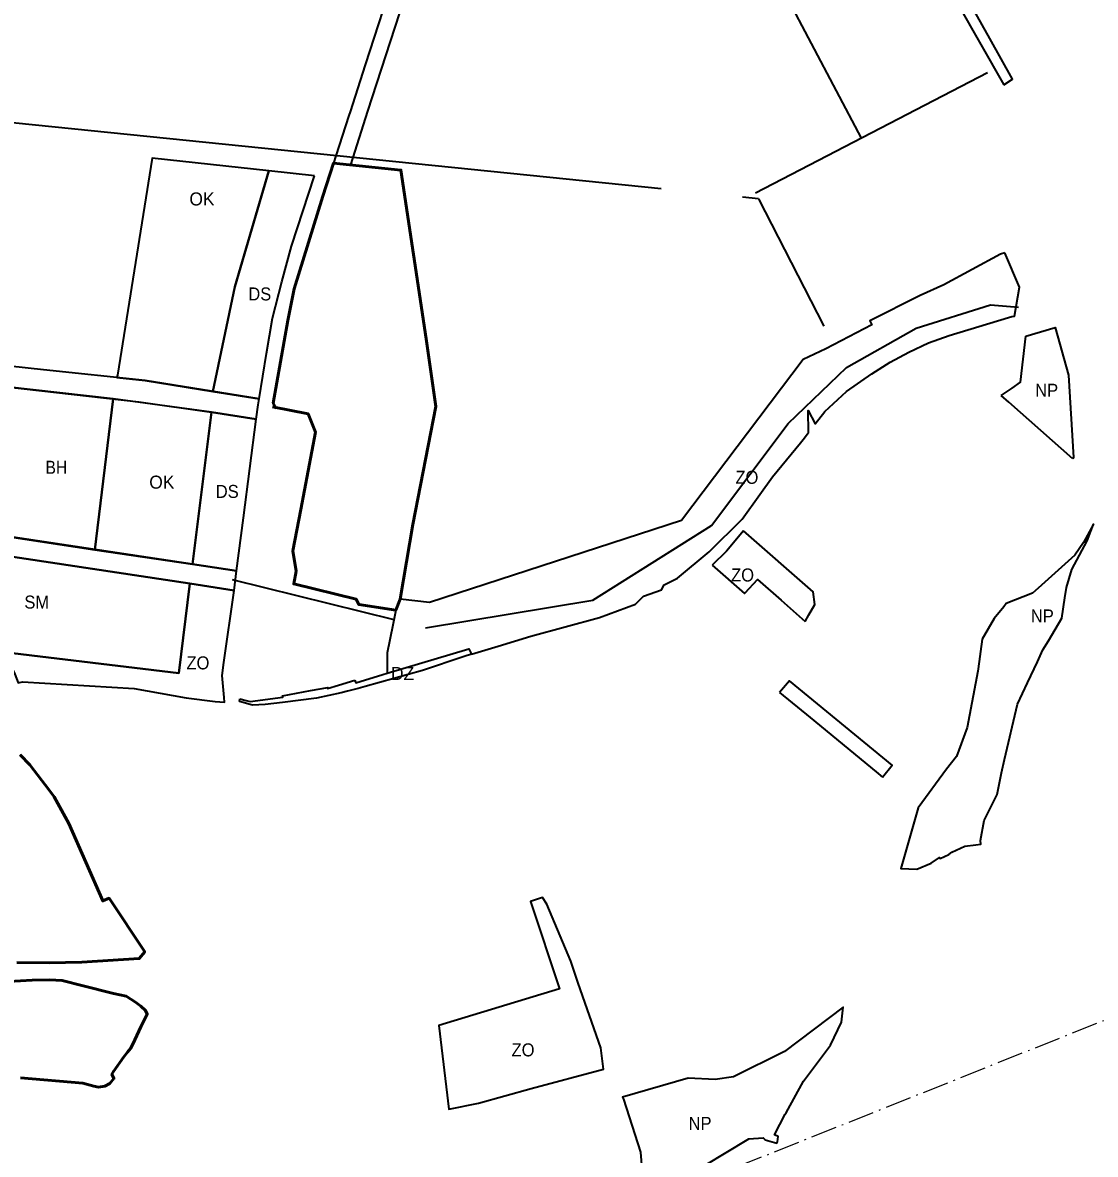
# Model space of a CAD drawing. Extents: x -650276 to -642489, y -1074311 to -1066658.
# Drawn here: x -646929 to -645941, y -1070271 to -1069228 of the extents above; entities that cross this region are included whole.
import ezdxf

# ---------------------------------------------------------------- set-up
doc = ezdxf.new("R2010")
doc.units = 0
doc.header["$LTSCALE"] = 4.8
doc.linetypes.add('DOT_DASHED', pattern=[7.7, 5, -1.2, 0.3, -1.2])
for name, color, linetype, lineweight in [('1', 7, 'Continuous', 35), ('13', 7, 'Continuous', 35), ('15', 7, 'Continuous', 35), ('18', 7, 'Continuous', 35), ('24', 7, 'Continuous', 35), ('25', 7, 'Continuous', 35), ('42', 7, 'Continuous', 35), ('48', 7, 'Continuous', 35), ('54', 7, 'Continuous', 35), ('55', 7, 'Continuous', 53), ('60', 7, 'Continuous', 53)]:
    doc.layers.add(name, color=color, linetype=linetype, lineweight=lineweight)
doc.layers.add('62', color=7, linetype='Continuous')

msp = doc.modelspace()

# ---------------------------------------------------------------- linework, layer by layer
at = {"layer": '1'}
msp.add_lwpolyline([(-646944.168, -1069563.743), (-647047.648, -1069552.245), (-647061.304, -1069551.773), (-647060.7, -1069683.894), (-646863, -1069714), (-646846, -1069575)], close=True, dxfattribs=at)
at = {"layer": '13'}
for points in [[(-646816.615, -1069558.064), (-646754.066, -1069567.993), (-646733.74, -1069471.688), (-646733.74, -1069471.688), (-646702.425, -1069364.771), (-646702.425, -1069364.771), (-646702.425, -1069364.771), (-646702.425, -1069364.771), (-646702.425, -1069364.771), (-646809.879, -1069353.002), (-646842.103, -1069553.182), (-646842.441, -1069555.283), (-646816.615, -1069558.064)], [(-646772.906, -1069727.176), (-646755.269, -1069587.04), (-646846, -1069575), (-646863, -1069714)]]:
    msp.add_lwpolyline(points, close=True, dxfattribs=at)
at = {"layer": '15'}
msp.add_line((-646142.68, -1069918.62), (-646136.88, -1069923.39), dxfattribs=at)
for points in [[(-646037.99, -1069242.88), (-646107, -1069119.41), (-646150.87, -1069037.64), (-646152.26, -1069038.76), (-646161.484, -1069046.228), (-646153.307, -1069059.947), (-646025.14, -1069285.394)], [(-646025.14, -1069285.394), (-646017.15, -1069280.19), (-646037.99, -1069242.88)], [(-646944.167, -1069563.743), (-646822.169, -1069577.72), (-646755.269, -1069587.04), (-646714.037, -1069593.585), (-646712.34, -1069580.49), (-646711.444, -1069574.771), (-646711.442, -1069574.759), (-646816.615, -1069558.064), (-646910.029, -1069548.006), (-646986.633, -1069539.757)], [(-647060.617, -1069702.116), (-646998.56, -1069711.443), (-646993.771, -1069712.163), (-646775.286, -1069745.022), (-646734.48, -1069751.35), (-646732.143, -1069733.308), (-646772.906, -1069727.176), (-646842.148, -1069716.763), (-647060.7, -1069683.894), (-647061.304, -1069551.773), (-647083.356, -1069551.018)], [(-646136.88, -1069923.39), (-646127.987, -1069912.574), (-646222.694, -1069834.722), (-646231.73, -1069845.42)], [(-646231.73, -1069845.42), (-646203.48, -1069868.65), (-646142.68, -1069918.62)]]:
    msp.add_lwpolyline(points, dxfattribs=at)
at = {"layer": '18'}
msp.add_lwpolyline([(-646785.437, -1069827.534), (-646775.286, -1069745.022), (-646993.771, -1069712.163), (-646981.92, -1069734.86), (-646946.369, -1069808.291)], close=True, dxfattribs=at)
msp.add_lwpolyline([(-646934.63, -1070094.24), (-646904.97, -1070094.52), (-646874.9, -1070094.1), (-646859.29, -1070093.1), (-646821.89, -1070090.7), (-646817.15, -1070084.76), (-646816.9, -1070084.45), (-646837.65, -1070053.22), (-646849.79, -1070035.17), (-646855.62, -1070037.66), (-646886.85, -1069966.26), (-646900.26, -1069941.64), (-646904.72, -1069935.84), (-646922.79, -1069912.31), (-646931.67, -1069902.89)], dxfattribs=at)
at = {"layer": '24'}
msp.add_line((-646772.907, -1069727.177), (-646732.143, -1069733.308), dxfattribs=at)
msp.add_lwpolyline([(-646660.526, -1069369.36), (-646702.425, -1069364.771), (-646733.74, -1069471.688), (-646754.066, -1069567.993), (-646711.442, -1069574.759), (-646704.68, -1069533.06), (-646699.07, -1069500.57), (-646690.51, -1069466.97), (-646681.5, -1069434.17)], close=True, dxfattribs=at)
for points in [[(-646725.82, -1069684.5), (-646714.037, -1069593.585), (-646755.269, -1069587.04), (-646772.907, -1069727.177)], [(-646732.143, -1069733.308), (-646725.82, -1069684.5), (-646725.82, -1069684.5)]]:
    msp.add_lwpolyline(points, dxfattribs=at)
at = {"layer": '25'}
msp.add_line((-646729.54, -1069853.69), (-646729.24, -1069851.41), dxfattribs=at)
for points in [[(-646515.63, -1069810.24), (-646522.32, -1069812.28), (-646560.92, -1069825.33), (-646613.65, -1069840.02), (-646620.06, -1069841.69), (-646629.83, -1069844.23), (-646635.93, -1069845.82), (-646658.5, -1069850.59), (-646689.73, -1069854.58), (-646705.87, -1069856.62), (-646717.66, -1069857.11), (-646729.54, -1069853.69)], [(-646593.34, -1069827.68), (-646518.19, -1069805.27), (-646515.63, -1069810.24)], [(-646623.31, -1069834.1), (-646622.54, -1069835.88), (-646622.19, -1069836.71), (-646597.29, -1069828.86), (-646593.34, -1069827.68)], [(-646729.24, -1069851.41), (-646723.5, -1069852.83), (-646719.82, -1069853.78), (-646689.63, -1069849.7), (-646689.8, -1069848.71), (-646664.22, -1069843.72), (-646648.18, -1069841.04), (-646648.28, -1069841.78), (-646638.34, -1069838.73), (-646623.31, -1069834.1)]]:
    msp.add_lwpolyline(points, dxfattribs=at)
at = {"layer": '42'}
msp.add_line((-646230.3, -1069760.5), (-646208.135, -1069779.937), dxfattribs=at)
for points in [[(-646589.56, -1069192.07), (-646601.41, -1069229.34), (-646613.6, -1069267.04), (-646627.59, -1069310.34), (-646628.66, -1069313.66), (-646640.715, -1069350.951), (-646642.89, -1069357.68), (-646626.774, -1069359.349), (-646611.107, -1069309.68), (-646577.878, -1069206.485)], [(-646023.96, -1069440.34), (-646028.16, -1069441.58), (-646080.35, -1069469.89), (-646102.15, -1069479.49), (-646148.5, -1069503), (-646146.8, -1069506.6), (-646189.17, -1069528.74), (-646209.9, -1069538.5), (-646321.973, -1069686.855), (-646554.262, -1069762.602), (-646581.489, -1069759.421), (-646585.51, -1069769.57)], [(-646017.63, -1069499.08), (-646017.63, -1069499.08), (-646015.16, -1069498.74), (-646010.65, -1069471.91), (-646023.96, -1069440.34)], [(-646491.18, -1069802.78), (-646491.18, -1069802.78), (-646460.97, -1069793.56), (-646397.74, -1069776.29), (-646364.67, -1069764.23), (-646357, -1069756.7), (-646340.48, -1069750.92), (-646337.97, -1069746.4), (-646325.92, -1069740.05), (-646296.64, -1069715.72), (-646266.27, -1069685.75), (-646250, -1069663.09), (-646238.19, -1069646.63), (-646212.43, -1069615.33), (-646210.03, -1069612.42), (-646205.9, -1069607.17), (-646205, -1069606.03), (-646205.25, -1069585.67), (-646198.82, -1069597.83), (-646190.07, -1069586.48), (-646169.9, -1069568.04), (-646146.81, -1069551.97), (-646129.87, -1069541.19), (-646112.56, -1069531.78), (-646094.39, -1069523.34), (-646075.48, -1069516.38), (-646020.75, -1069500), (-646017.63, -1069499.08)], [(-646265.02, -1069696.43), (-646280.5, -1069715.27), (-646293.76, -1069728)], [(-646208.135, -1069779.937), (-646204.6, -1069773.78), (-646199.17, -1069764.33), (-646200.67, -1069752.88), (-646265.02, -1069696.43)], [(-646293.76, -1069728), (-646263.929, -1069754.309), (-646263.36, -1069753.69), (-646252.07, -1069741.41), (-646230.3, -1069760.5)], [(-646585.51, -1069769.57), (-646588.25, -1069783.37), (-646593.34, -1069808.99), (-646593.34, -1069827.68)], [(-646593.34, -1069827.68), (-646518.19, -1069805.27), (-646515.63, -1069810.24), (-646491.18, -1069802.78)], [(-646417.23, -1070113.25), (-646424.17, -1070093.21), (-646446.21, -1070040.55), (-646450.22, -1070034.31), (-646461.415, -1070037.991), (-646434.503, -1070118.512), (-646545.78, -1070152.41), (-646536.47, -1070229.65), (-646509.31, -1070224.11), (-646460.8, -1070210.57)], [(-646460.8, -1070210.57), (-646393.97, -1070192.69), (-646396.51, -1070173.06), (-646417.23, -1070113.25)]]:
    msp.add_lwpolyline(points, dxfattribs=at)
msp.add_lwpolyline([(-646775.286, -1069745.022), (-646785.437, -1069827.534), (-646946.369, -1069808.291), (-646936.6, -1069828.47), (-646933.39, -1069836.51), (-646929.67, -1069835.68), (-646826.63, -1069841.84), (-646778.74, -1069850.44), (-646751.8, -1069853.72), (-646743.31, -1069854.26), (-646743.7, -1069850.07), (-646745.56, -1069829.84), (-646743.85, -1069817.72), (-646734.48, -1069751.35)], close=True, dxfattribs=at)
at = {"layer": '48'}
for points in [[(-646027.49, -1069571.79), (-646017.39, -1069564.94), (-646009.52, -1069559.6), (-646004.7, -1069517.16)], [(-646004.7, -1069517.16), (-645977.73, -1069509.11), (-645965.36, -1069552.99), (-645960.78, -1069628.91), (-645961.36, -1069630.05)], [(-645961.36, -1069630.05), (-646020.4, -1069578.04), (-646027.49, -1069571.79)], [(-646321.24, -1070293.85), (-646259.91, -1070256.89), (-646246.71, -1070255.96), (-646245.02, -1070257.65), (-646234.17, -1070260.88), (-646233.69, -1070259.57), (-646233.36, -1070257.04), (-646233.06, -1070254.74), (-646236.44, -1070253.13), (-646226.42, -1070234.23), (-646225.7, -1070232.93), (-646209.55, -1070203.85), (-646184.67, -1070170.61), (-646174.62, -1070149.28), (-646173.2, -1070135.64), (-646227.29, -1070176.24), (-646274.26, -1070199.6), (-646291.14, -1070202.1), (-646315.95, -1070201.09), (-646376.5, -1070218.32), (-646375.52, -1070220.21), (-646359.89, -1070269.01), (-646357.73, -1070296.13)]]:
    msp.add_lwpolyline(points, dxfattribs=at)
msp.add_lwpolyline([(-646050.68, -1069985.78), (-646046.28, -1069985.18), (-646046.63, -1069982.04), (-646043.2, -1069963.46), (-646031.24, -1069939.45), (-646030.62, -1069936.3), (-646027.3, -1069919.47), (-646024.41, -1069907.23), (-646012.37, -1069856.22), (-646003.18, -1069836.56), (-645993.96, -1069817.23), (-645989.01, -1069806.25), (-645983.89, -1069797.86), (-645971.7, -1069777.05), (-645968.78, -1069758.13), (-645967.35, -1069748.81), (-645962.48, -1069732.04), (-645948.22, -1069705.79), (-645942.41, -1069690.26), (-645951.52, -1069707.28), (-645959.63, -1069718.95), (-645993.22, -1069749.24), (-645998.57, -1069754.06), (-646022.72, -1069763.59), (-646025.11, -1069766.63), (-646034.02, -1069777.19), (-646044.94, -1069796.35), (-646048.71, -1069823.79), (-646049, -1069825.93), (-646058.71, -1069877.82), (-646068.5, -1069904.5), (-646077.78, -1069916.11), (-646104.04, -1069951.75), (-646119.95, -1070007.73), (-646105.35, -1070008.18), (-646091.87, -1070002.66), (-646084.39, -1069997.53), (-646083.67, -1069998.4), (-646075.69, -1069994.68), (-646073.1, -1069992.61), (-646060.94, -1069987.19)], close=True, dxfattribs=at)
at = {"layer": '54'}
for p, q in [((-646261, -1069137), (-646156.539, -1069334.511)), ((-646253.953, -1069385.091), (-646040, -1069274)), ((-646340.757, -1069381.428), (-647038.68, -1069310.312)), ((-646251.153, -1069390.558), (-646266.005, -1069389.045)), ((-646251.153, -1069390.558), (-646191, -1069508)), ((-646736.301, -1069741.493), (-646587.205, -1069778.112))]:
    msp.add_line(p, q, dxfattribs=at)
msp.add_lwpolyline([(-646558.043, -1069786.029), (-646403.749, -1069760.313), (-646294.458, -1069691.739), (-646223.741, -1069597.448), (-646170.167, -1069546.017), (-646105.878, -1069509.587), (-646037.303, -1069488.157), (-646011.588, -1069490.3)], dxfattribs=at)
at = {"layer": '55', "linetype": 'DOT_DASHED', "lineweight": 25}
msp.add_line((-647060.176, -1070597.455), (-645765.418, -1070080.935), dxfattribs=at)
at = {"layer": '60'}
for points in [[(-646695.61, -1069583.8), (-646698.4, -1069578.93), (-646684.95, -1069502.53), (-646679.13, -1069473.51), (-646652.72, -1069388.08), (-646642.89, -1069357.68), (-646580.797, -1069364.111), (-646557.39, -1069519.61), (-646548.41, -1069582.03), (-646569.86, -1069690.67), (-646581.489, -1069759.421), (-646585.51, -1069769.57), (-646619.49, -1069764.46), (-646622, -1069759.34), (-646679.46, -1069745.37), (-646677.36, -1069733.65), (-646680.28, -1069714.83), (-646673, -1069676.8), (-646666.26, -1069641.2), (-646659.52, -1069605.53), (-646666.36, -1069588.57), (-646698.96, -1069582.26)], [(-646931.67, -1069902.89), (-646922.79, -1069912.31), (-646904.72, -1069935.84), (-646900.26, -1069941.64), (-646886.85, -1069966.26), (-646855.62, -1070037.66), (-646849.79, -1070035.17), (-646816.9, -1070084.45), (-646821.89, -1070090.7), (-646874.9, -1070094.1), (-646904.97, -1070094.52), (-646934.63, -1070094.24)], [(-646941.99, -1070111.74), (-646920.68, -1070110.58), (-646904.66, -1070110.24), (-646892.87, -1070110.82), (-646873.5, -1070115.8), (-646845.78, -1070122.84), (-646834.04, -1070125.34), (-646825.4, -1070130.78), (-646820.35, -1070134.43), (-646816.06, -1070138.5), (-646814.53, -1070141.96), (-646820.51, -1070153.68), (-646827.95, -1070169.52), (-646829.87, -1070173.61), (-646832.62, -1070177.08), (-646836.06, -1070181.31), (-646845.76, -1070194.67), (-646847.17, -1070197.38), (-646845.3, -1070201.3), (-646849.15, -1070205.9), (-646853.67, -1070208.44), (-646859.54, -1070209.09), (-646863.66, -1070208.37), (-646874.04, -1070205.5), (-646931.25, -1070200.56)]]:
    msp.add_lwpolyline(points, dxfattribs=at)

# ---------------------------------------------------------------- texts
at = {"layer": '62'}
for s, p in [('OK', (-646775.694, -1069396.644)), ('OK', (-646812.694, -1069657.644)), ('DZ', (-646589.843, -1069833.949))]:
    msp.add_text(s, height=12, dxfattribs=at).set_placement(p)
for s, width, p in [('DS', 0.95, (-646721.423, -1069484.188)), ('NP', 0.95, (-645996.15, -1069572.972)), ('BH', 0.9, (-646908.386, -1069643.937)), ('ZO', 0.95, (-646272.423, -1069653.188)), ('DS', 0.95, (-646751.423, -1069666.188)), ('ZO', 0.95, (-646276.423, -1069743.188)), ('SM', 0.95, (-646927.837, -1069768.153)), ('NP', 0.95, (-646000.15, -1069780.972)), ('ZO', 0.95, (-646778.423, -1069824.188)), ('ZO', 0.95, (-646478.758, -1070180.853)), ('NP', 0.95, (-646315.631, -1070248.579))]:
    msp.add_text(s, height=12, dxfattribs=dict(at, width=width)).set_placement(p)

doc.saveas('drawing.dxf')
